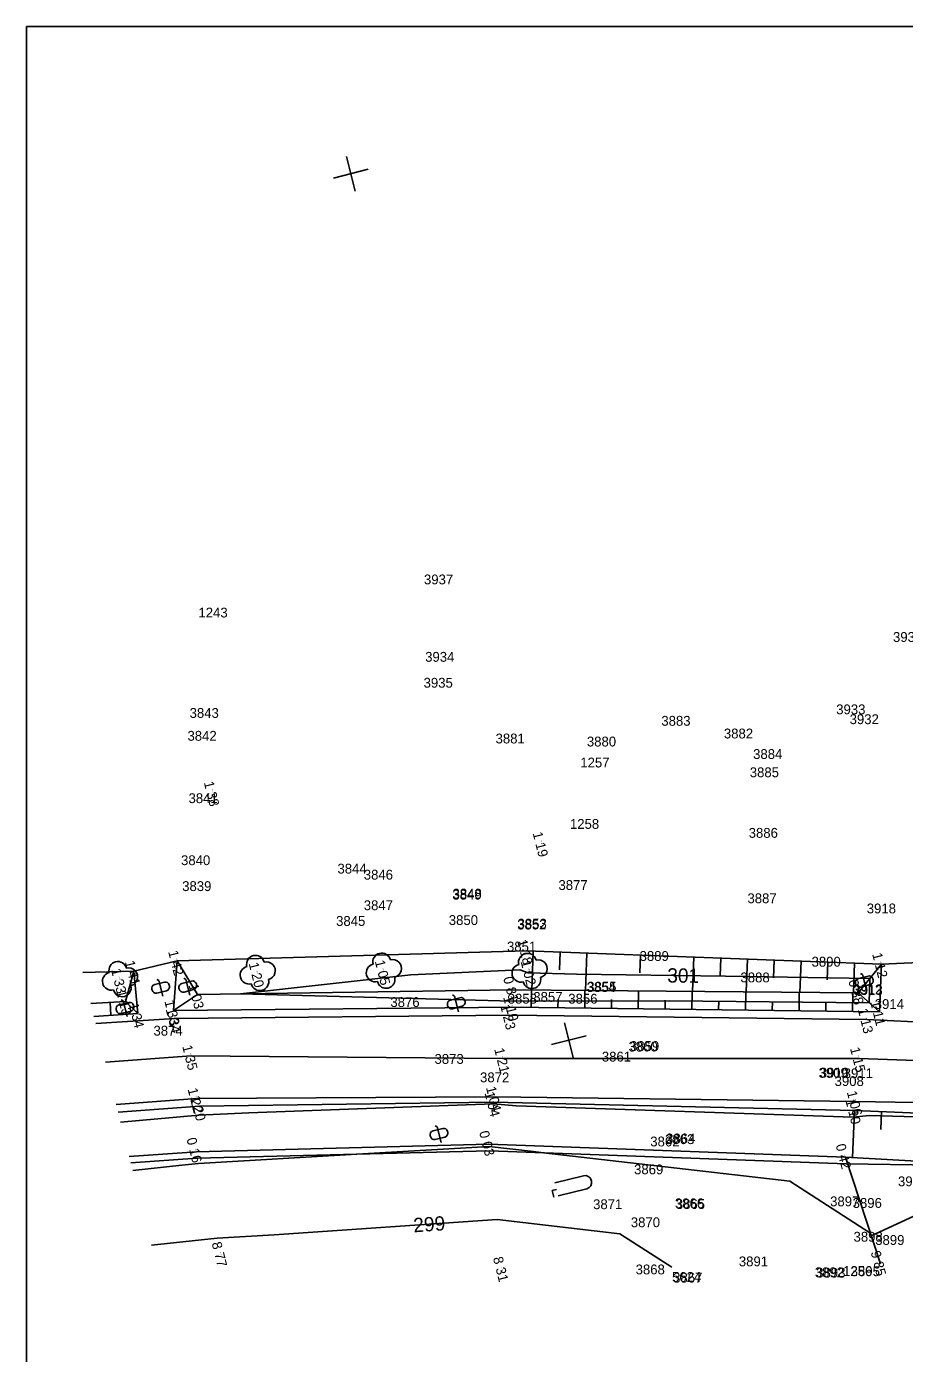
# Model space of a CAD drawing. Extents: x -740053 to -737517, y -1033516 to -1032488.
# Drawn here: x -739409.2 to -739360.1, y -1032580.7 to -1032506.5 of the extents above; entities that cross this region are included whole.
import ezdxf

# ---------------------------------------------------------------- set-up
doc = ezdxf.new("R2010")
doc.units = 0
for name, color, linetype in [('bod-cislo', 7, 'Continuous'), ('bod-oznac', 7, 'Continuous'), ('bod-vyska', 7, 'Continuous'), ('bod-vyska100', 7, 'Continuous'), ('Contours', 7, 'Continuous'), ('Contours highlighted', 7, 'Continuous'), ('Contours text', 7, 'Continuous'), ('ctv-sit', 7, 'Continuous'), ('Hranice-zelene', 7, 'Continuous'), ('osa-komunikace', 7, 'Continuous'), ('Predmety bez rozlišeni', 7, 'Continuous'), ('silnice', 7, 'Continuous'), ('Technické šrafy', 7, 'Continuous'), ('Terenni-hrana', 7, 'Continuous'), ('Znacky-kultury', 7, 'Continuous')]:
    doc.layers.add(name, color=color, linetype=linetype)

# ---------------------------------------------------------------- blocks, each defined once
blk = doc.blocks.new('POINT_DISPLAY')
blk.add_line((0, 0), (0, 0))
blk = doc.blocks.new('p_strom')
for centre, start, end in [((0, 1), 0, 180), ((-1, 0), 90, 270), ((1, 0), 270, 90), ((0, -1), 180, 0)]:
    blk.add_arc(centre, 1, start, end)
at = {"rotation": -180}
blk.add_blockref('POINT_DISPLAY', (0, 0), dxfattribs=at)
blk = doc.blocks.new('p_leslis')
for p, q in [((-0.05, 4.51), (0.05, 4.51)), ((-0.75, 0.5), (-0.75, 3.81)), ((0.75, 0.5), (0.75, 3.81)), ((0, 0), (0, 0.5)), ((0, 0), (0.75, 0))]:
    blk.add_line(p, q)
for centre, start, end in [((-0.05, 3.81), 90, 180), ((0.05, 3.81), 0, 90)]:
    blk.add_arc(centre, 0.7, start, end)
blk = doc.blocks.new('p_neplod')
for p, q in [((-0.82, 0), (-0.99, -0.18)), ((1, 0), (-0.82, 0)), ((-0.49, 0.56), (-0.49, -0.55)), ((0.05, 1.01), (-0.04, 1.01)), ((0.5, -0.55), (0.5, 0.56)), ((-0.04, -1), (0.05, -1))]:
    blk.add_line(p, q)
for centre, start, end in [((-0.04, 0.56), 90, 180), ((0.05, 0.56), 0, 90), ((-0.04, -0.55), 180, 270), ((0.05, -0.55), 270, 0)]:
    blk.add_arc(centre, 0.45, start, end)
blk = doc.blocks.new('ctvsit')
for p, q in [((0, -2), (0, 2)), ((2, 0), (-2, 0))]:
    blk.add_line(p, q)

msp = doc.modelspace()

# ---------------------------------------------------------------- linework, layer by layer
at = {"layer": 'Contours'}
for points in [[(-739362.072, -1032561.109), (-739373.25, -1032560.991), (-739382.037, -1032561.021), (-739397.267, -1032560.602), (-739387.738, -1032559.533), (-739381.632, -1032559.263), (-739381.171, -1032559.428), (-739378.455, -1032559.502), (-739370.123, -1032559.612), (-739362.043, -1032559.747), (-739362.072, -1032561.109)], [(-739403.98, -1032567.793), (-739399.604, -1032567.388), (-739396.802, -1032567.262), (-739383.11, -1032566.764), (-739381.829, -1032566.87), (-739362.962, -1032567.515), (-739362.052, -1032567.418), (-739353.659, -1032567.65)], [(-739402.249, -1032574.668), (-739398.581, -1032574.272), (-739395.392, -1032574.083), (-739382.902, -1032573.236), (-739376.027, -1032574.03), (-739373.117, -1032575.908)]]:
    msp.add_lwpolyline(points, dxfattribs=at)
at = {"layer": 'Contours highlighted'}
msp.add_lwpolyline([(-739403.299, -1032570.496), (-739400.56, -1032570.2), (-739399.624, -1032570.099), (-739390.755, -1032569.573), (-739383.351, -1032569.14), (-739380.871, -1032569.427), (-739380.305, -1032569.493), (-739366.512, -1032571.086), (-739362.044, -1032573.97), (-739361.961, -1032574.147), (-739354.274, -1032570.607), (-739353.782, -1032570.469), (-739352.822, -1032570.487), (-739328.276, -1032574.302), (-739303.936, -1032577.649)], dxfattribs=at)
at = {"layer": 'Hranice-zelene'}
for p, q in [((-739383.325, -1032569.382), (-739399.698, -1032569.802)), ((-739363.363, -1032570.111), (-739383.325, -1032569.382)), ((-739399.698, -1032569.802), (-739403.407, -1032570.07)), ((-739353.795, -1032570.266), (-739363.363, -1032570.111))]:
    msp.add_line(p, q, dxfattribs=at)
at = {"layer": 'osa-komunikace'}
for p, q in [((-739400.028, -1032564.065), (-739404.828, -1032564.424)), ((-739382.56, -1032564.226), (-739400.028, -1032564.065)), ((-739362.629, -1032564.22), (-739382.56, -1032564.226)), ((-739362.629, -1032564.22), (-739353.276, -1032564.547))]:
    msp.add_line(p, q, dxfattribs=at)
at = {"layer": 'Predmety bez rozlišeni'}
for p, q in [((-739409.249, -1032506.478), (-739304.249, -1032506.478)), ((-739409.249, -1032654.978), (-739409.249, -1032506.478))]:
    msp.add_line(p, q, dxfattribs=at)
at = {"layer": 'silnice'}
for p, q in [((-739400.953, -1032561.988), (-739405.372, -1032562.264)), ((-739382.222, -1032561.8), (-739400.953, -1032561.988)), ((-739362.196, -1032562.049), (-739382.222, -1032561.8)), ((-739362.196, -1032562.049), (-739353.246, -1032562.456)), ((-739399.723, -1032566.464), (-739404.233, -1032566.789)), ((-739383.02, -1032566.373), (-739399.723, -1032566.464)), ((-739362.816, -1032566.629), (-739383.02, -1032566.373)), ((-739362.816, -1032566.629), (-739353.554, -1032566.803))]:
    msp.add_line(p, q, dxfattribs=at)
at = {"layer": 'Technické šrafy'}
for p, q in [((-739380.877, -1032558.211), (-739380.959, -1032560.397)), ((-739379.378, -1032558.267), (-739379.416, -1032559.266)), ((-739377.879, -1032558.323), (-739377.958, -1032560.423)), ((-739374.881, -1032558.435), (-739374.919, -1032559.434)), ((-739371.884, -1032558.547), (-739371.955, -1032560.475)), ((-739370.385, -1032558.602), (-739370.422, -1032559.602)), ((-739368.886, -1032558.658), (-739368.954, -1032560.501)), ((-739367.387, -1032558.714), (-739367.424, -1032559.714)), ((-739365.888, -1032558.77), (-739365.953, -1032560.527)), ((-739364.389, -1032558.826), (-739364.426, -1032559.825)), ((-739362.89, -1032558.882), (-739362.952, -1032560.553)), ((-739380.999, -1032561.367), (-739380.986, -1032560.397)), ((-739377.999, -1032561.405), (-739377.987, -1032560.423)), ((-739374.999, -1032561.443), (-739374.987, -1032560.449)), ((-739372, -1032561.482), (-739371.987, -1032560.475)), ((-739369, -1032561.52), (-739368.987, -1032560.501)), ((-739366, -1032561.558), (-739365.987, -1032560.527)), ((-739363, -1032561.597), (-739362.987, -1032560.553)), ((-739404.522, -1032561.803), (-739404.569, -1032561.083)), ((-739379.499, -1032561.386), (-739379.493, -1032560.898)), ((-739376.499, -1032561.424), (-739376.493, -1032560.93)), ((-739373.499, -1032561.463), (-739373.493, -1032560.962)), ((-739370.5, -1032561.501), (-739370.493, -1032560.994)), ((-739367.5, -1032561.539), (-739367.493, -1032561.026)), ((-739364.5, -1032561.577), (-739364.494, -1032561.059)), ((-739362.886, -1032567.131), (-739362.997, -1032569.768)), ((-739361.387, -1032567.194), (-739361.429, -1032568.193))]:
    msp.add_line(p, q, dxfattribs=at)
at = {"layer": 'Terenni-hrana'}
for p, q in [((-739381.263, -1032558.197), (-739400.815, -1032558.767)), ((-739361.391, -1032558.938), (-739381.263, -1032558.197)), ((-739403.24, -1032559.336), (-739400.815, -1032558.767)), ((-739400.815, -1032558.767), (-739401.024, -1032561.542)), ((-739400.815, -1032558.767), (-739399.675, -1032560.635)), ((-739361.391, -1032558.938), (-739362.695, -1032560.555)), ((-739361.391, -1032558.938), (-739361.5, -1032561.616)), ((-739357.367, -1032558.781), (-739361.391, -1032558.938)), ((-739403.24, -1032559.336), (-739406.089, -1032559.415)), ((-739403.71, -1032561.032), (-739403.24, -1032559.336)), ((-739403.71, -1032561.032), (-739403.24, -1032559.336)), ((-739403.025, -1032561.706), (-739403.24, -1032559.336)), ((-739382.021, -1032560.388), (-739399.675, -1032560.635)), ((-739362.695, -1032560.555), (-739382.021, -1032560.388)), ((-739362.695, -1032560.555), (-739361.5, -1032561.616)), ((-739405.653, -1032561.147), (-739403.71, -1032561.032)), ((-739403.025, -1032561.706), (-739403.71, -1032561.032)), ((-739399.675, -1032560.635), (-739401.024, -1032561.542)), ((-739403.025, -1032561.706), (-739405.472, -1032561.866)), ((-739382.046, -1032561.353), (-739401.024, -1032561.542)), ((-739361.5, -1032561.616), (-739382.046, -1032561.353)), ((-739399.572, -1032566.9), (-739404.122, -1032567.229)), ((-739383.1, -1032566.672), (-739399.572, -1032566.9)), ((-739362.886, -1032567.131), (-739383.1, -1032566.672)), ((-739362.886, -1032567.131), (-739353.652, -1032567.518)), ((-739399.738, -1032569.437), (-739403.497, -1032569.709)), ((-739383.365, -1032569.017), (-739399.738, -1032569.437)), ((-739363.403, -1032569.746), (-739383.365, -1032569.017)), ((-739361.446, -1032575.719), (-739363.403, -1032569.746)), ((-739353.795, -1032570.266), (-739363.403, -1032569.746))]:
    msp.add_line(p, q, dxfattribs=at)

# ---------------------------------------------------------------- block references
at = {"layer": 'bod-oznac', "rotation": -75.86979040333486}
for p in [(-739398.815, -1032549.303), (-739380.397, -1032552.173), (-739381.263, -1032558.197), (-739400.815, -1032558.767), (-739361.391, -1032558.938), (-739404.015, -1032559.779), (-739403.24, -1032559.336), (-739396.306, -1032559.437), (-739389.243, -1032559.309), (-739381.082, -1032559.327), (-739382.021, -1032560.388), (-739362.695, -1032560.555), (-739403.71, -1032561.032), (-739399.675, -1032560.635), (-739403.025, -1032561.706), (-739401.024, -1032561.542), (-739400.953, -1032561.988), (-739382.222, -1032561.8), (-739382.046, -1032561.353), (-739362.196, -1032562.049), (-739361.5, -1032561.616), (-739400.028, -1032564.065), (-739382.56, -1032564.226), (-739362.629, -1032564.22), (-739399.723, -1032566.464), (-739383.02, -1032566.373), (-739399.572, -1032566.9), (-739383.1, -1032566.672), (-739362.886, -1032567.131), (-739362.816, -1032566.629), (-739399.738, -1032569.437), (-739383.365, -1032569.017), (-739363.403, -1032569.746), (-739398.341, -1032575.231), (-739382.592, -1032576.062), (-739361.446, -1032575.719)]:
    msp.add_blockref('POINT_DISPLAY', p, dxfattribs=at)
at = {"layer": 'ctv-sit', "xscale": 0.49999999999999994, "yscale": 0.5, "rotation": 104.13020959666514}
for p in [(-739391.096, -1032514.712), (-739378.89, -1032563.199)]:
    msp.add_blockref('ctvsit', p, dxfattribs=at)
at = {"layer": 'Znacky-kultury', "xscale": 0.49999999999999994}
for name, p, yscale, rotation in [('p_strom', (-739396.306, -1032559.437), 0.4999999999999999, -75.86979040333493), ('p_strom', (-739389.243, -1032559.309), 0.4999999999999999, -75.86979040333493), ('p_strom', (-739381.082, -1032559.327), 0.4999999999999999, -75.86979040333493), ('p_strom', (-739404.015, -1032559.779), 0.4999999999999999, -75.86979040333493), ('p_neplod', (-739401.745, -1032560.255), 0.5, -75.86979040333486), ('p_neplod', (-739400.227, -1032560.193), 0.5, -75.86979040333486), ('p_neplod', (-739362.347, -1032559.916), 0.5, -75.86979040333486), ('p_neplod', (-739385.193, -1032561.126), 0.5, -75.86979040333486), ('p_neplod', (-739403.74, -1032561.395), 0.5, -75.86979040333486), ('p_neplod', (-739386.161, -1032568.445), 0.5, -75.86979040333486), ('p_leslis', (-739379.819, -1032571.61), 0.5, -75.86979040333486)]:
    msp.add_blockref(name, p, dxfattribs=dict(at, yscale=yscale, rotation=rotation))

# ---------------------------------------------------------------- texts
at = {"layer": 'bod-cislo'}
for s, p in [('3937', (-739386.998, -1032537.693)), ('1243', (-739399.624, -1032539.545)), ('3938', (-739360.738, -1032540.913)), ('3934', (-739386.931, -1032542.023)), ('3935', (-739387.018, -1032543.473)), ('3843', (-739400.118, -1032545.163)), ('3933', (-739363.918, -1032544.963)), ('3932', (-739363.168, -1032545.513)), ('3883', (-739373.708, -1032545.603)), ('3842', (-739400.238, -1032546.443)), ('3881', (-739382.989, -1032546.593)), ('3880', (-739377.878, -1032546.763)), ('3882', (-739370.208, -1032546.313)), ('3884', (-739368.571, -1032547.463)), ('1257', (-739378.246, -1032547.937)), ('3885', (-739368.758, -1032548.483)), ('3841', (-739400.179, -1032549.933)), ('1258', (-739378.826, -1032551.373)), ('3886', (-739368.818, -1032551.873)), ('3840', (-739400.598, -1032553.403)), ('3844', (-739391.841, -1032553.873)), ('3846', (-739390.368, -1032554.213)), ('3839', (-739400.535, -1032554.853)), ('3877', (-739379.468, -1032554.793)), ('3847', (-739390.368, -1032555.923)), ('3849', (-739385.405, -1032555.333)), ('3848', (-739385.398, -1032555.273)), ('3887', (-739368.888, -1032555.533)), ('3918', (-739362.208, -1032556.103)), ('3845', (-739391.918, -1032556.803)), ('3850', (-739385.608, -1032556.753)), ('3852', (-739381.778, -1032557.003)), ('3853', (-739381.758, -1032556.953)), ('3851', (-739382.349, -1032558.233)), ('3889', (-739374.925, -1032558.763)), ('3890', (-739365.298, -1032559.083)), ('3888', (-739369.278, -1032559.963)), ('3857', (-739380.878, -1032561.053)), ('3854', (-739377.891, -1032560.503)), ('3855', (-739377.858, -1032560.483)), ('3912', (-739362.978, -1032560.633)), ('3913', (-739362.948, -1032560.673)), ('3876', (-739388.878, -1032561.343)), ('3858', (-739382.308, -1032561.153)), ('3856', (-739378.918, -1032561.153)), ('3914', (-739361.761, -1032561.453)), ('3874', (-739402.141, -1032562.943)), ('3860', (-739375.548, -1032563.833)), ('3859', (-739375.465, -1032563.803)), ('3873', (-739386.408, -1032564.523)), ('3861', (-739377.039, -1032564.393)), ('3872', (-739383.858, -1032565.553)), ('3909', (-739364.905, -1032565.303)), ('3910', (-739364.838, -1032565.293)), ('3911', (-739363.499, -1032565.323)), ('3908', (-739364.008, -1032565.763)), ('3862', (-739374.328, -1032569.143)), ('3863', (-739373.498, -1032569.013)), ('3864', (-739373.441, -1032568.973)), ('3869', (-739375.235, -1032570.703)), ('3901', (-739360.459, -1032571.373)), ('3871', (-739377.529, -1032572.653)), ('3866', (-739372.948, -1032572.603)), ('3865', (-739372.898, -1032572.643)), ('3897', (-739364.258, -1032572.493)), ('3896', (-739362.998, -1032572.583)), ('3870', (-739375.418, -1032573.663)), ('3898', (-739362.948, -1032574.473)), ('3899', (-739361.735, -1032574.653)), ('3891', (-739369.369, -1032575.853)), ('3868', (-739375.148, -1032576.303)), ('5624', (-739373.111, -1032576.723)), ('3892', (-739365.118, -1032576.463)), ('3893', (-739365.038, -1032576.483)), ('1256', (-739363.536, -1032576.39)), ('3895', (-739363.108, -1032576.403)), ('3867', (-739373.048, -1032576.763))]:
    msp.add_text(s, height=0.55, dxfattribs=at).set_placement(p)
at = {"layer": 'bod-vyska'}
for s, p in [('1 38', (-739399.325, -1032548.779)), ('1 19', (-739380.917, -1032551.612)), ('1 18', (-739381.782, -1032557.635)), ('1 42', (-739401.325, -1032558.244)), ('1 12', (-739361.91, -1032558.377)), ('1 41', (-739403.75, -1032558.813)), ('1 20', (-739396.815, -1032558.913)), ('1 05', (-739389.753, -1032558.785)), ('1 02', (-739381.592, -1032558.803)), ('1 33', (-739404.525, -1032559.256)), ('0 81', (-739382.569, -1032559.713)), ('0 88', (-739363.244, -1032559.88)), ('1 13', (-739404.229, -1032560.471)), ('1 03', (-739400.185, -1032560.112)), ('1 34', (-739403.535, -1032561.182)), ('1 33', (-739401.534, -1032561.019)), ('1 23', (-739382.732, -1032561.277)), ('1 10', (-739382.566, -1032560.792)), ('1 11', (-739362.02, -1032561.054)), ('1 34', (-739401.463, -1032561.465)), ('1 13', (-739362.715, -1032561.487)), ('1 35', (-739400.538, -1032563.542)), ('1 21', (-739383.07, -1032563.703)), ('1 15', (-739363.148, -1032563.659)), ('1 22', (-739400.233, -1032565.94)), ('1 20', (-739400.082, -1032566.377)), ('1 04', (-739383.61, -1032566.148)), ('1 04', (-739383.53, -1032565.85)), ('1 10', (-739363.405, -1032566.569)), ('1 06', (-739363.326, -1032566.105)), ('0 16', (-739400.296, -1032568.723)), ('0 03', (-739383.913, -1032568.342)), ('0 42', (-739363.951, -1032569.071)), ('8 77', (-739398.889, -1032574.556)), ('8 31', (-739383.14, -1032575.386)), ('9 85', (-739361.991, -1032575.056))]:
    msp.add_text(s, height=0.55, rotation=284.13021, dxfattribs=at).set_placement(p)
at = {"layer": 'bod-vyska100'}
for s, p in [('301 38', (-739398.887, -1032549.156)), ('301 19', (-739380.47, -1032552.023)), ('301 18', (-739381.335, -1032558.046)), ('301 42', (-739400.887, -1032558.62)), ('301 12', (-739361.463, -1032558.788)), ('301 33', (-739404.087, -1032559.632)), ('301 41', (-739403.311, -1032559.19)), ('301 20', (-739396.377, -1032559.29)), ('301 05', (-739389.314, -1032559.162)), ('301 02', (-739381.153, -1032559.18)), ('301 03', (-739399.746, -1032560.489)), ('300 81', (-739382.094, -1032560.234)), ('300 88', (-739362.769, -1032560.402)), ('301 13', (-739403.782, -1032560.882)), ('301 10', (-739382.118, -1032561.203)), ('301 34', (-739403.096, -1032561.559)), ('301 33', (-739401.096, -1032561.395)), ('301 34', (-739401.025, -1032561.842)), ('301 23', (-739382.294, -1032561.653)), ('301 13', (-739362.268, -1032561.898)), ('301 11', (-739361.573, -1032561.465)), ('301 35', (-739400.099, -1032563.919)), ('301 21', (-739382.632, -1032564.079)), ('301 15', (-739362.701, -1032564.07)), ('301 22', (-739399.795, -1032566.317)), ('301 04', (-739383.171, -1032566.525)), ('301 04', (-739383.091, -1032566.226)), ('301 06', (-739362.888, -1032566.482)), ('301 20', (-739399.644, -1032566.753)), ('301 10', (-739362.958, -1032566.98)), ('300 16', (-739399.812, -1032569.28)), ('300 03', (-739383.438, -1032568.864)), ('300 42', (-739363.476, -1032569.592)), ('298 77', (-739398.414, -1032575.078)), ('298 31', (-739382.665, -1032575.908)), ('299 85', (-739361.519, -1032575.566))]:
    msp.add_text(s, height=0.05, rotation=284.13021, dxfattribs=at).set_placement(p)
at = {"layer": 'Contours text'}
for s, rotation, p in [('301', 359.24587, (-739373.381, -1032559.969)), ('299', 3.87749, (-739387.567, -1032573.953))]:
    msp.add_text(s, height=0.8, rotation=rotation, dxfattribs=at).set_placement(p)

doc.saveas('drawing.dxf')
